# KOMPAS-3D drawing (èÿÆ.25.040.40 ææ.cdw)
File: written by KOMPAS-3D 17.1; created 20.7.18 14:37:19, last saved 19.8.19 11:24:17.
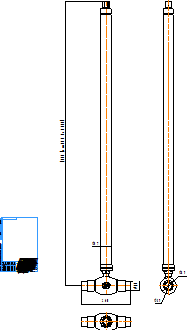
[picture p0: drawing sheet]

Sheet 1: A4, portrait

Title block, sheet 1: name: КШТ.22.050.40 С/С; sheets: 1; sheet format: A4; stored path: C:\Users\kka\KOMPAS_Work\Модели кранов для исследований\DN50\С удлинением\КШТ.22.050.40 СС.cdw

Views: Вид 1, Проекционный вид 2
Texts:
  kka
  adl
  (от 250 до 5000)
  Рама для чертежей
  Лит-Масса-Масштаб
  Материал-Предприятие
  Масштаб
  Изм.
  Лист
  № докум.
  Подп.
  Дата
  Лит.
  Разраб.
  Пров.
  Т.контр.
  Листов
  Внимание! Данный продукт является объектом авторского права ООО «Торговый Дом АДЛ».
  Запрещается изменение, копирование, распространение
  (в том числе путем копирования на другие сайты и ресурсы в Интернете)
  или любое иное использование информации и объектов без предварительного
  согласия правообладателя (ООО «Торговый Дом АДЛ»).
  Н.контр.
  Утв.
  ООО "Торговый дом АДЛ"
  Изменение
  Номер документа
  Подпись
  Обозначение документа
  Наименование изделия
  Масса изделия по ГОСТ 2.109-73
  Порядковый номер листа
  Общее количество листов в документе
  Характер работы, выполненной лицом, подписавшим документ
  Наименование или индекс предприятия, выпускающего документ
  Инв. № подл.
  Подп. и дата
  Взам. инв. №
  Инв. № дубл.
  Инвентарный номер подлинника по ГОСТ 2.501-68
  Подпись принявшего подлинник в отдел технической документации
  Инвентарный номер подлинника, взамен которого выпущен данный подлинник
  Инвентарный номер дубликата по ГОСТ 2.502-68
  Подпись принявшего дубликат в отдел технической документации
  Справ. №
  Перв. примен.
  Обозначение документа, взамен или на основании которого выпущен данный документ
  Обозначение документа, в котором впервые записан данный документ
  Подпись лица, копировавшего чертеж
  Обозначение формата листа
  !Рама для чертежа
Dimensions and other numbers on the sheet: 260; 48; 1500; 57; 1:1; 1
